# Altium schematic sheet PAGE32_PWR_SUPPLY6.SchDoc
size 431 x 304 mm; SheetNumber: 28; SheetTotal: 28
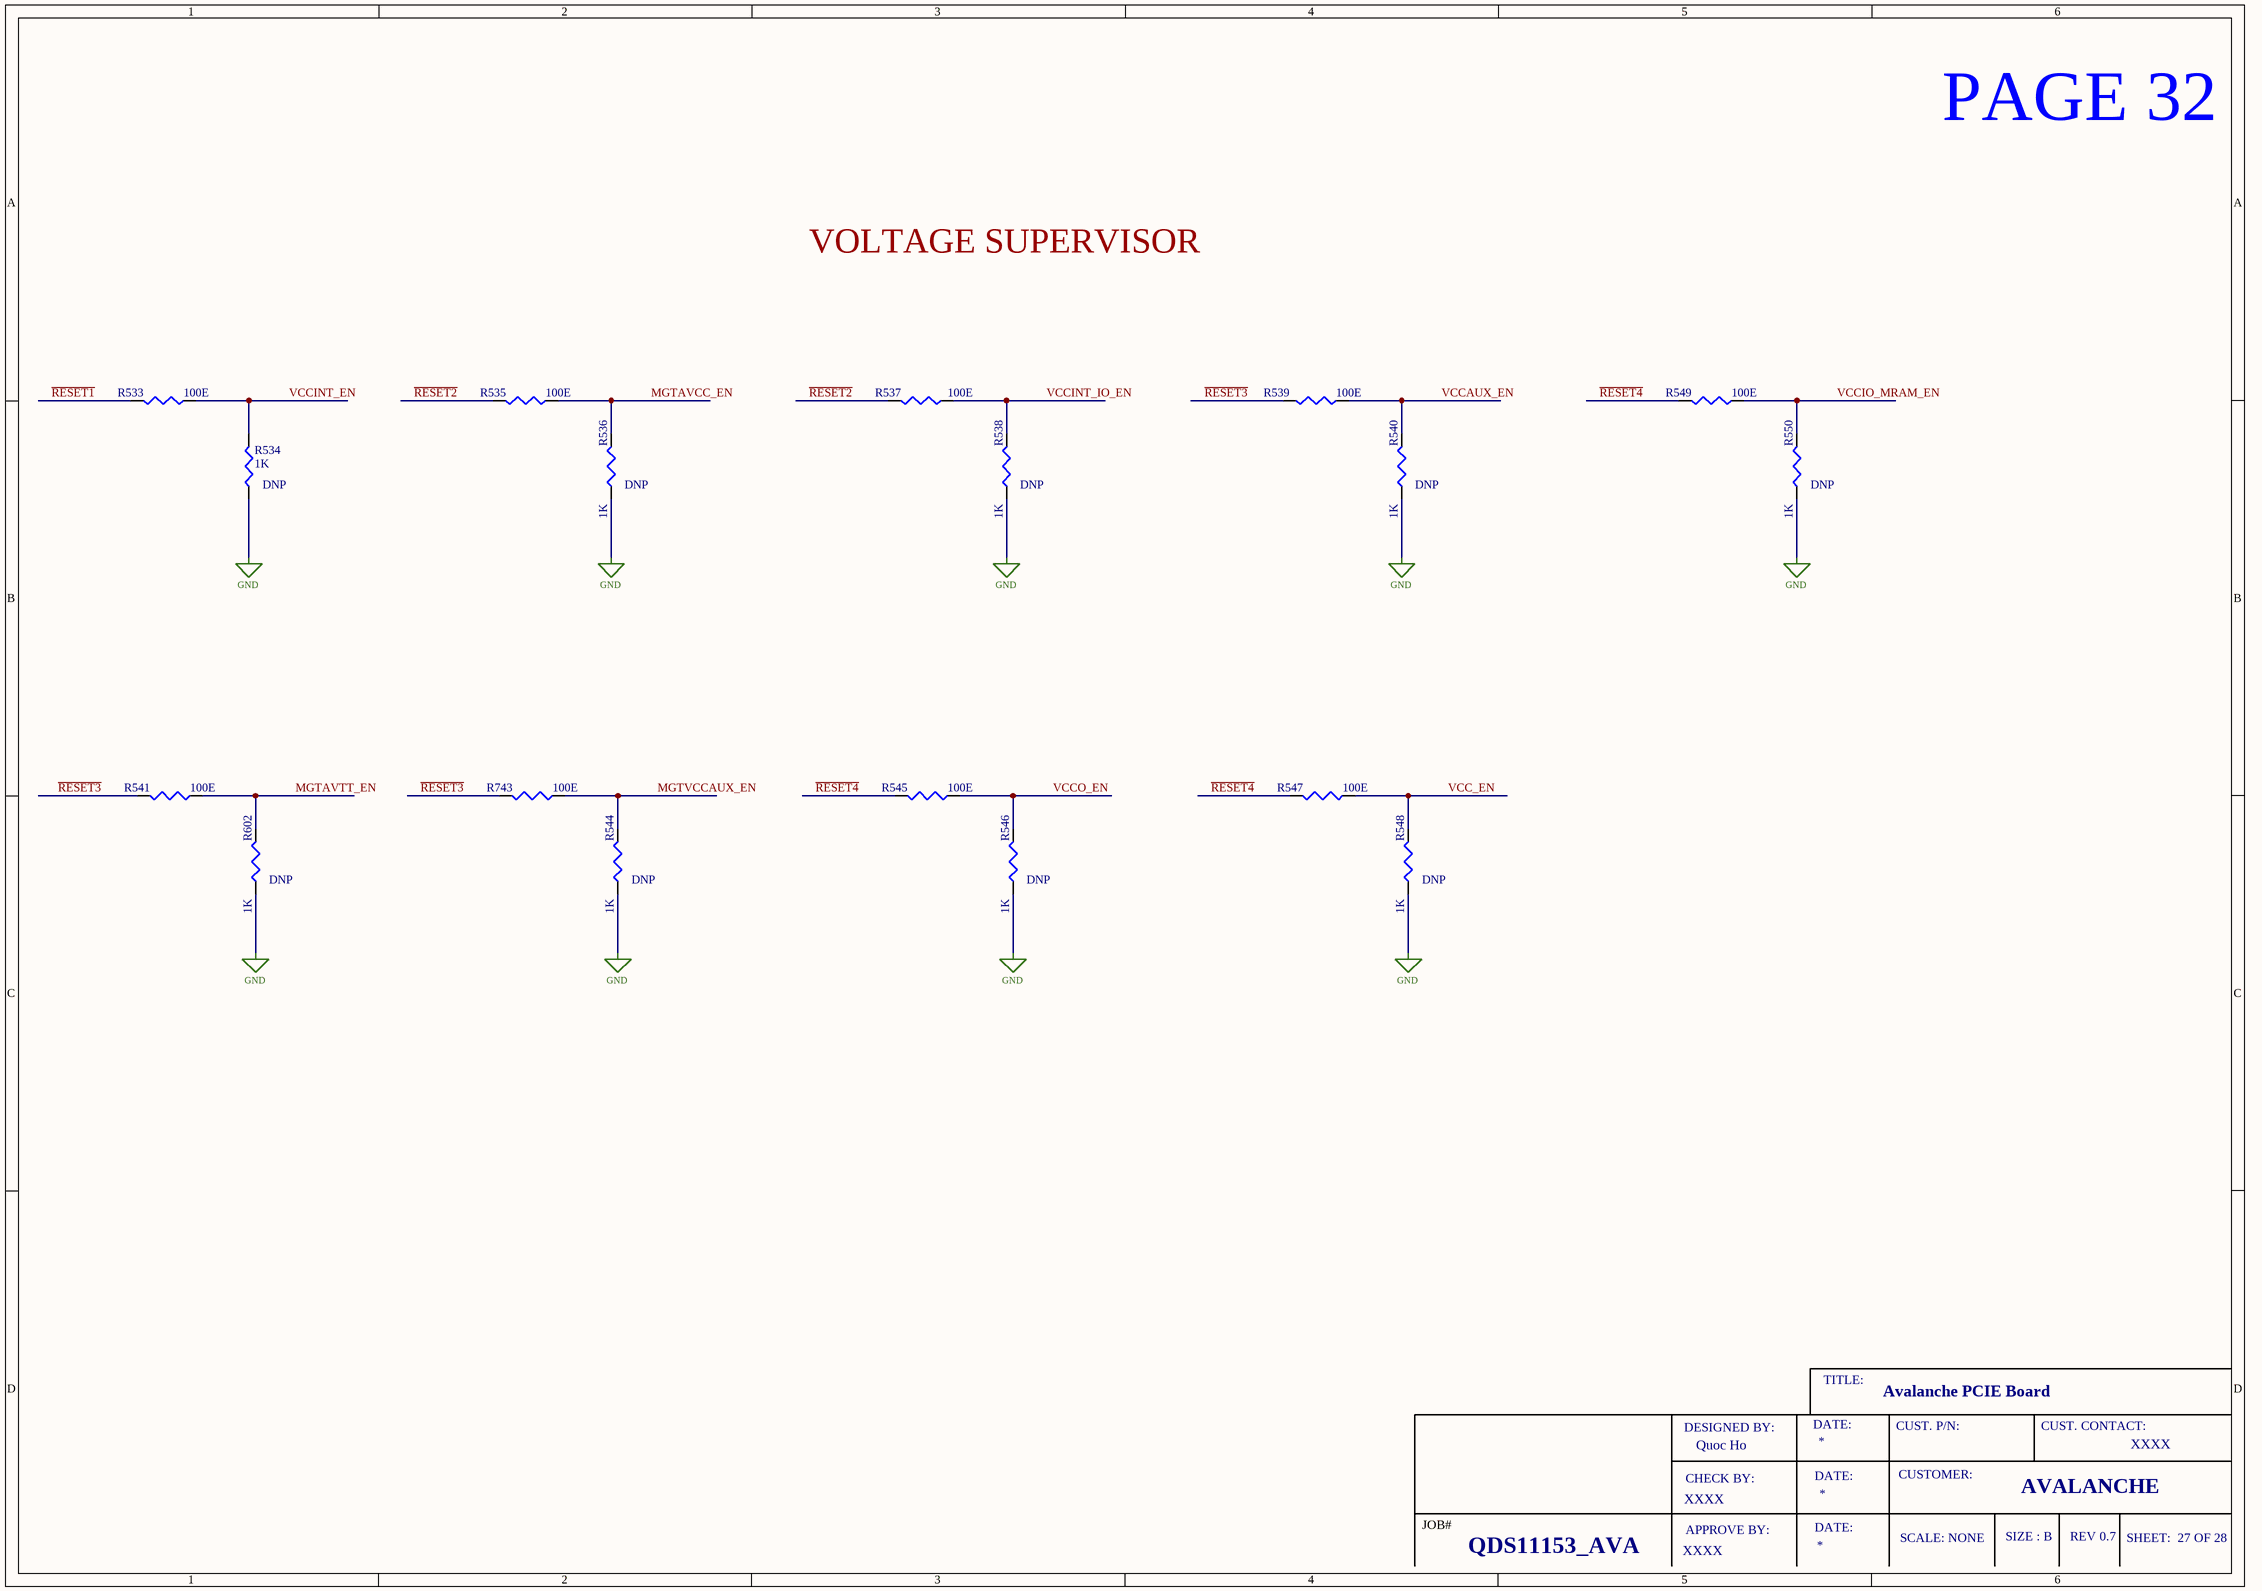
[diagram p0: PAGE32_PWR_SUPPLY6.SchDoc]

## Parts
R533  100E  [RN_0402]
R534  1K  [RN_0402]
R535  100E  [RN_0402]
R536  1K  [RN_0402]
R537  100E  [RN_0402]
R538  1K  [RN_0402]
R539  100E  [RN_0402]
R540  1K  [RN_0402]
R541  100E  [RN_0402]
R544  1K  [RN_0402]
R545  100E  [RN_0402]
R546  1K  [RN_0402]
R547  100E  [RN_0402]
R548  1K  [RN_0402]
R549  100E  [RN_0402]
R550  1K  [RN_0402]
R602  1K  [RN_0402]
R743  100E  [RN_0402]

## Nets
GND: R534.1 R536.1 R538.1 R540.1 R544.1 R546.1 R548.1 R550.1 R602.1
MGTAVCC_EN: R535.1 R536.2
MGTAVTT_EN: R541.1 R602.2
MGTVCCAUX_EN: R544.2 R743.1
~{RESET1}: R533.2
~{RESET2}: R535.2 R537.2
~{RESET3}: R539.2 R541.2 R743.2
~{RESET4}: R545.2 R547.2 R549.2
VCC_EN: R547.1 R548.2
VCCAUX_EN: R539.1 R540.2
VCCINT_EN: R533.1 R534.2
VCCINT_IO_EN: R537.1 R538.2
VCCIO_MRAM_EN: R549.1 R550.2
VCCO_EN: R545.1 R546.2

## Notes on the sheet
- PAGE 32
- VOLTAGE SUPERVISOR
- (near R534) DNP
- (near R536) DNP
- (near R538) DNP
- (near R540) DNP
- (near R550) DNP
- (near R602) DNP
- (near R544) DNP
- (near R546) DNP
- (near R548) DNP
- TITLE:
- Avalanche PCIE Board
- DESIGNED BY:
- CHECK BY:
- Quoc Ho
- DATE:
- CUST. P/N:
- CUSTOMER:
- CUST. CONTACT:
- XXXX
- JOB#
- APPROVE BY:
- SCALE: NONE
- SIZE : B
- AVALANCHE
- REV 0.7
- SHEET:  27 OF 28
- QDS11153_AVA

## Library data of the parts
R533 R535 R537 R539 R541 R545 R547 R549 R743 = RES: RES 100 OHM 1% 1/16W 0402; Manufacturer Part Number: RC0402FR-07100RL; Manufacturer: YAGEO
R534 R536 R538 R540 R544 R546 R548 R550 R602 = RES: RES 1K OHM 1% 1/16W 0402; Manufacturer Part Number: RC0402FR-131KL; Manufacturer: YAGEO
